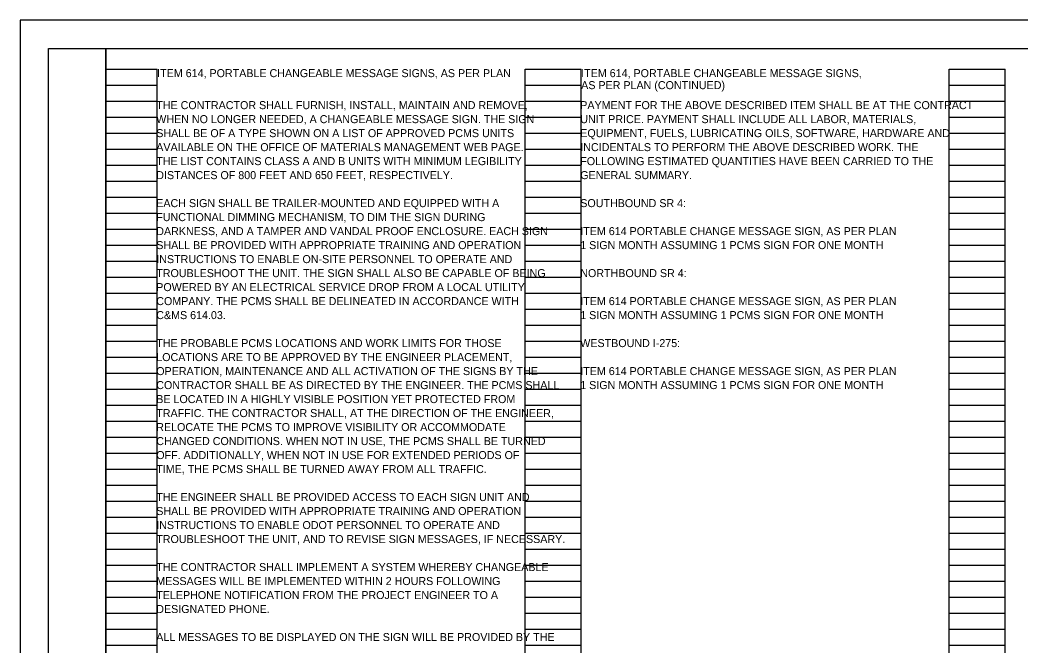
# Model space of a CAD drawing. Extents: x 0 to 50.1, y 0 to 22.
# Drawn here: x 0 to 17.52, y 11.04 to 22 of the extents above; entities that cross this region are included whole.
import ezdxf

# ---------------------------------------------------------------- set-up
doc = ezdxf.new("R2010")
doc.units = 0
for name, color, linetype in [('SH_Border', 7, 'Continuous'), ('SH_Cut_Line', 7, 'Continuous'), ('SH_Data', 7, 'Continuous'), ('SH_Text', 7, 'Continuous')]:
    doc.layers.add(name, color=color, linetype=linetype)

msp = doc.modelspace()

# ---------------------------------------------------------------- linework, layer by layer
at = {"layer": 'SH_Border'}
for points in [[(0.5, 21.5), (1.5, 21.5), (1.5, 0.5), (0.5, 0.5)], [(1.5, 21.5), (33.5, 21.5), (33.5, 0.5), (1.5, 0.5)]]:
    msp.add_lwpolyline(points, close=True, dxfattribs=at)
at = {"layer": 'SH_Cut_Line'}
msp.add_lwpolyline([(0, 0), (34, 0), (34, 22), (0, 22)], close=True, dxfattribs=at)
at = {"layer": 'SH_Data'}
for p, q in [((1.5, 0.98), (1.5, 21.14)), ((1.5, 21.14), (2.4, 21.14)), ((2.4, 0.98), (2.4, 21.14)), ((8.84, 0.98), (8.84, 21.14)), ((8.84, 21.14), (9.82, 21.14)), ((9.82, 0.98), (9.82, 21.14)), ((16.26, 0.98), (16.26, 21.14)), ((16.26, 21.14), (17.24, 21.14)), ((17.24, 0.98), (17.24, 21.14)), ((1.5, 20.86), (2.4, 20.86)), ((8.84, 20.86), (9.82, 20.86)), ((16.26, 20.86), (17.24, 20.86)), ((1.5, 20.58), (2.4, 20.58)), ((8.84, 20.58), (9.82, 20.58)), ((16.26, 20.58), (17.24, 20.58)), ((1.5, 20.3), (2.4, 20.3)), ((8.84, 20.3), (9.82, 20.3)), ((16.26, 20.3), (17.24, 20.3)), ((1.5, 20.02), (2.4, 20.02)), ((8.84, 20.02), (9.82, 20.02)), ((16.26, 20.02), (17.24, 20.02)), ((1.5, 19.74), (2.4, 19.74)), ((8.84, 19.74), (9.82, 19.74)), ((16.26, 19.74), (17.24, 19.74)), ((1.5, 19.46), (2.4, 19.46)), ((8.84, 19.46), (9.82, 19.46)), ((16.26, 19.46), (17.24, 19.46)), ((1.5, 19.18), (2.4, 19.18)), ((8.84, 19.18), (9.82, 19.18)), ((16.26, 19.18), (17.24, 19.18)), ((1.5, 18.9), (2.4, 18.9)), ((8.84, 18.9), (9.82, 18.9)), ((16.26, 18.9), (17.24, 18.9)), ((1.5, 18.62), (2.4, 18.62)), ((8.84, 18.62), (9.82, 18.62)), ((16.26, 18.62), (17.24, 18.62)), ((1.5, 18.34), (2.4, 18.34)), ((8.84, 18.34), (9.82, 18.34)), ((16.26, 18.34), (17.24, 18.34)), ((1.5, 18.06), (2.4, 18.06)), ((8.84, 18.06), (9.82, 18.06)), ((16.26, 18.06), (17.24, 18.06)), ((1.5, 17.78), (2.4, 17.78)), ((8.84, 17.78), (9.82, 17.78)), ((16.26, 17.78), (17.24, 17.78)), ((1.5, 17.5), (2.4, 17.5)), ((8.84, 17.5), (9.82, 17.5)), ((16.26, 17.5), (17.24, 17.5)), ((1.5, 17.22), (2.4, 17.22)), ((8.84, 17.22), (9.82, 17.22)), ((16.26, 17.22), (17.24, 17.22)), ((1.5, 16.94), (2.4, 16.94)), ((8.84, 16.94), (9.82, 16.94)), ((16.26, 16.94), (17.24, 16.94)), ((1.5, 16.66), (2.4, 16.66)), ((8.84, 16.66), (9.82, 16.66)), ((16.26, 16.66), (17.24, 16.66)), ((1.5, 16.38), (2.4, 16.38)), ((8.84, 16.38), (9.82, 16.38)), ((16.26, 16.38), (17.24, 16.38)), ((1.5, 16.1), (2.4, 16.1)), ((8.84, 16.1), (9.82, 16.1)), ((16.26, 16.1), (17.24, 16.1)), ((1.5, 15.82), (2.4, 15.82)), ((8.84, 15.82), (9.82, 15.82)), ((16.26, 15.82), (17.24, 15.82)), ((1.5, 15.54), (2.4, 15.54)), ((8.84, 15.54), (9.82, 15.54)), ((16.26, 15.54), (17.24, 15.54)), ((1.5, 15.26), (2.4, 15.26)), ((8.84, 15.26), (9.82, 15.26)), ((16.26, 15.26), (17.24, 15.26)), ((1.5, 14.98), (2.4, 14.98)), ((8.84, 14.98), (9.82, 14.98)), ((16.26, 14.98), (17.24, 14.98)), ((1.5, 14.7), (2.4, 14.7)), ((8.84, 14.7), (9.82, 14.7)), ((16.26, 14.7), (17.24, 14.7)), ((1.5, 14.42), (2.4, 14.42)), ((8.84, 14.42), (9.82, 14.42)), ((16.26, 14.42), (17.24, 14.42)), ((1.5, 14.14), (2.4, 14.14)), ((8.84, 14.14), (9.82, 14.14)), ((16.26, 14.14), (17.24, 14.14)), ((1.5, 13.86), (2.4, 13.86)), ((8.84, 13.86), (9.82, 13.86)), ((16.26, 13.86), (17.24, 13.86)), ((1.5, 13.58), (2.4, 13.58)), ((8.84, 13.58), (9.82, 13.58)), ((16.26, 13.58), (17.24, 13.58)), ((1.5, 13.3), (2.4, 13.3)), ((8.84, 13.3), (9.82, 13.3)), ((16.26, 13.3), (17.24, 13.3)), ((1.5, 13.02), (2.4, 13.02)), ((8.84, 13.02), (9.82, 13.02)), ((16.26, 13.02), (17.24, 13.02)), ((1.5, 12.74), (2.4, 12.74)), ((8.84, 12.74), (9.82, 12.74)), ((16.26, 12.74), (17.24, 12.74)), ((1.5, 12.46), (2.4, 12.46)), ((8.84, 12.46), (9.82, 12.46)), ((16.26, 12.46), (17.24, 12.46)), ((1.5, 12.18), (2.4, 12.18)), ((8.84, 12.18), (9.82, 12.18)), ((16.26, 12.18), (17.24, 12.18)), ((1.5, 11.9), (2.4, 11.9)), ((8.84, 11.9), (9.82, 11.9)), ((16.26, 11.9), (17.24, 11.9)), ((1.5, 11.62), (2.4, 11.62)), ((8.84, 11.62), (9.82, 11.62)), ((16.26, 11.62), (17.24, 11.62)), ((1.5, 11.34), (2.4, 11.34)), ((8.84, 11.34), (9.82, 11.34)), ((16.26, 11.34), (17.24, 11.34)), ((1.5, 11.06), (2.4, 11.06)), ((8.84, 11.06), (9.82, 11.06)), ((16.26, 11.06), (17.24, 11.06))]:
    msp.add_line(p, q, dxfattribs=at)

# ---------------------------------------------------------------- texts
at = {"layer": 'SH_Text'}
for s, p in [('ITEM 614, PORTABLE CHANGEABLE MESSAGE SIGNS, AS PER PLAN', (2.4, 21)), ('ITEM 614, PORTABLE CHANGEABLE MESSAGE SIGNS, ', (9.82, 21)), ('AS PER PLAN (CONTINUED)', (9.82, 20.79)), ('THE CONTRACTOR SHALL FURNISH, INSTALL, MAINTAIN AND REMOVE, ', (2.384, 20.44)), ('PAYMENT FOR THE ABOVE DESCRIBED ITEM SHALL BE AT THE CONTRACT ', (9.804, 20.44)), ('WHEN NO LONGER NEEDED, A CHANGEABLE MESSAGE SIGN. THE SIGN ', (2.384, 20.195)), ('UNIT PRICE. PAYMENT SHALL INCLUDE ALL LABOR, MATERIALS, ', (9.804, 20.195)), ('SHALL BE OF A TYPE SHOWN ON A LIST OF APPROVED PCMS UNITS ', (2.384, 19.95)), ('EQUIPMENT, FUELS, LUBRICATING OILS, SOFTWARE, HARDWARE AND ', (9.804, 19.95)), ('AVAILABLE ON THE OFFICE OF MATERIALS MANAGEMENT WEB PAGE. ', (2.384, 19.705)), ('INCIDENTALS TO PERFORM THE ABOVE DESCRIBED WORK. THE ', (9.804, 19.705)), ('THE LIST CONTAINS CLASS A AND B UNITS WITH MINIMUM LEGIBILITY ', (2.384, 19.46)), ('FOLLOWING ESTIMATED QUANTITIES HAVE BEEN CARRIED TO THE ', (9.804, 19.46)), ('DISTANCES OF 800 FEET AND 650 FEET, RESPECTIVELY.', (2.384, 19.215)), ('GENERAL SUMMARY.', (9.804, 19.215)), ('EACH SIGN SHALL BE TRAILER-MOUNTED AND EQUIPPED WITH A ', (2.384, 18.725)), ('SOUTHBOUND SR 4:', (9.804, 18.725)), ('FUNCTIONAL DIMMING MECHANISM, TO DIM THE SIGN DURING', (2.384, 18.48)), ('DARKNESS, AND A TAMPER AND VANDAL PROOF ENCLOSURE. EACH SIGN ', (2.384, 18.235)), ('ITEM 614 PORTABLE CHANGE MESSAGE SIGN, AS PER PLAN', (9.804, 18.235)), ('SHALL BE PROVIDED WITH APPROPRIATE TRAINING AND OPERATION ', (2.384, 17.99)), ('1 SIGN MONTH ASSUMING 1 PCMS SIGN FOR ONE MONTH', (9.804, 17.99)), ('INSTRUCTIONS TO ENABLE ON-SITE PERSONNEL TO OPERATE AND ', (2.384, 17.745)), ('TROUBLESHOOT THE UNIT. THE SIGN SHALL ALSO BE CAPABLE OF BEING ', (2.384, 17.5)), ('NORTHBOUND SR 4:', (9.804, 17.5)), ('POWERED BY AN ELECTRICAL SERVICE DROP FROM A LOCAL UTILITY ', (2.384, 17.255)), ('COMPANY. THE PCMS SHALL BE DELINEATED IN ACCORDANCE WITH ', (2.384, 17.01)), ('ITEM 614 PORTABLE CHANGE MESSAGE SIGN, AS PER PLAN', (9.804, 17.01)), ('C&MS 614.03.', (2.384, 16.765)), ('1 SIGN MONTH ASSUMING 1 PCMS SIGN FOR ONE MONTH', (9.804, 16.765)), ('THE PROBABLE PCMS LOCATIONS AND WORK LIMITS FOR THOSE', (2.384, 16.275)), ('WESTBOUND I-275:', (9.804, 16.275)), ('LOCATIONS ARE TO BE APPROVED BY THE ENGINEER PLACEMENT, ', (2.384, 16.03)), ('OPERATION, MAINTENANCE AND ALL ACTIVATION OF THE SIGNS BY THE ', (2.384, 15.785)), ('ITEM 614 PORTABLE CHANGE MESSAGE SIGN, AS PER PLAN', (9.804, 15.785)), ('CONTRACTOR SHALL BE AS DIRECTED BY THE ENGINEER. THE PCMS SHALL ', (2.384, 15.54)), ('1 SIGN MONTH ASSUMING 1 PCMS SIGN FOR ONE MONTH', (9.804, 15.54)), ('BE LOCATED IN A HIGHLY VISIBLE POSITION YET PROTECTED FROM ', (2.384, 15.295)), ('TRAFFIC. THE CONTRACTOR SHALL, AT THE DIRECTION OF THE ENGINEER, ', (2.384, 15.05)), ('RELOCATE THE PCMS TO IMPROVE VISIBILITY OR ACCOMMODATE ', (2.384, 14.805)), ('CHANGED CONDITIONS. WHEN NOT IN USE, THE PCMS SHALL BE TURNED', (2.384, 14.56)), ('OFF. ADDITIONALLY, WHEN NOT IN USE FOR EXTENDED PERIODS OF ', (2.384, 14.315)), ('TIME, THE PCMS SHALL BE TURNED AWAY FROM ALL TRAFFIC.', (2.384, 14.07)), ('THE ENGINEER SHALL BE PROVIDED ACCESS TO EACH SIGN UNIT AND ', (2.384, 13.58)), ('SHALL BE PROVIDED WITH APPROPRIATE TRAINING AND OPERATION ', (2.384, 13.335)), ('INSTRUCTIONS TO ENABLE ODOT PERSONNEL TO OPERATE AND ', (2.384, 13.09)), ('TROUBLESHOOT THE UNIT, AND TO REVISE SIGN MESSAGES, IF NECESSARY.', (2.384, 12.845)), ('THE CONTRACTOR SHALL IMPLEMENT A SYSTEM WHEREBY CHANGEABLE ', (2.384, 12.355)), ('MESSAGES WILL BE IMPLEMENTED WITHIN 2 HOURS FOLLOWING ', (2.384, 12.11)), ('TELEPHONE NOTIFICATION FROM THE PROJECT ENGINEER TO A ', (2.384, 11.865)), ('DESIGNATED PHONE.', (2.384, 11.62)), ('ALL MESSAGES TO BE DISPLAYED ON THE SIGN WILL BE PROVIDED BY THE ', (2.384, 11.13))]:
    msp.add_text(s, height=0.14, dxfattribs=at).set_placement(p)

doc.saveas('drawing.dxf')
